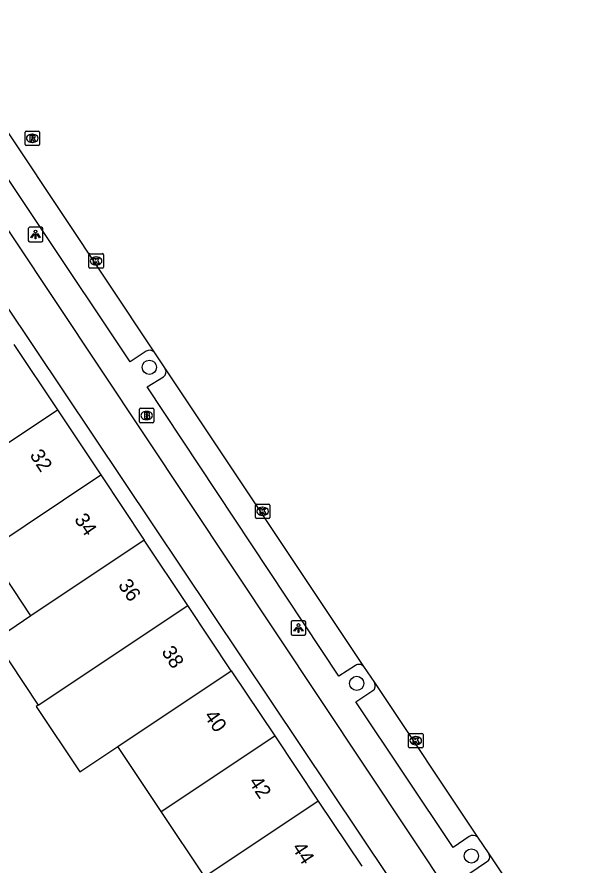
# Model space of a CAD drawing. Extents: x 158352 to 159489, y 383828 to 384597.
# Drawn here: x 158924.3 to 158963.6, y 384353.8 to 384412.1 of the extents above; entities that cross this region are included whole.
import ezdxf

# ---------------------------------------------------------------- set-up
doc = ezdxf.new("R2010")
doc.units = 0
for name, color, linetype in [('IMGEO_Boom', 7, 'Continuous'), ('IMGEO_Brandkraan', 7, 'Continuous'), ('IMGEO_Erf', 7, 'Continuous'), ('IMGEO_Kolk', 7, 'Continuous'), ('IMGEO_Lichtpunt', 7, 'Continuous'), ('IMGEO_Pand', 7, 'Continuous'), ('IMGEO_Pand_nummerreeks', 7, 'Continuous'), ('IMGEO_Rijbaan_lokaal_gesloten', 7, 'Continuous'), ('IMGEO_Rioolput', 7, 'Continuous'), ('IMGEO_Voetpad_open', 7, 'Continuous')]:
    doc.layers.add(name, color=color, linetype=linetype)

msp = doc.modelspace()

# ---------------------------------------------------------------- linework, layer by layer
at = {"layer": 'IMGEO_Boom'}
for centre in [(158933.366, 384388.02), (158947.643, 384366.263), (158955.538, 384354.394)]:
    msp.add_circle(centre, 0.489, dxfattribs=at)
at = {"layer": 'IMGEO_Brandkraan'}
for p, q in [((158932.682, 384384.272), (158932.682, 384385.124)), ((158932.757, 384385.198), (158933.609, 384385.198)), ((158933.17, 384384.978), (158933.195, 384384.978)), ((158933.683, 384385.124), (158933.683, 384384.272)), ((158933.609, 384384.198), (158932.757, 384384.198)), ((158933.193, 384384.418), (158933.168, 384384.418))]:
    msp.add_line(p, q, dxfattribs=at)
for points in [[(158932.682, 384384.272), (158932.682, 384385.124)], [(158932.757, 384385.198), (158933.609, 384385.198)], [(158933.03, 384384.898), (158933.03, 384384.498), (158933.243, 384384.498)], [(158933.261, 384384.898), (158933.03, 384384.898)], [(158933.209, 384384.817), (158933.155, 384384.817), (158933.155, 384384.741)], [(158933.155, 384384.741), (158933.208, 384384.741)], [(158933.217, 384384.665), (158933.155, 384384.665), (158933.155, 384384.584)], [(158933.683, 384385.124), (158933.683, 384384.272)], [(158933.609, 384384.198), (158932.757, 384384.198)], [(158933.155, 384384.584), (158933.217, 384384.584)]]:
    msp.add_lwpolyline(points, dxfattribs=at)
for centre, radius, start, end in [((158932.759, 384385.122), 0.0765, 91.55205, 178.44795), ((158932.759, 384385.122), 0.0765, 91.55205, 178.44795), ((158933.21, 384384.779), 0.0379, 267.82845, 90.93552), ((158933.218, 384384.624), 0.0404, 269.87594, 90.50774), ((158933.265, 384384.753), 0.145, 59.4692, 91.53667), ((158933.29, 384384.8), 0.0922, 285.51372, 58.15012), ((158933.295, 384384.608), 0.105, 301.31148, 78.98903), ((158933.607, 384385.122), 0.0765, 1.55205, 88.44795), ((158933.607, 384385.122), 0.0765, 1.55205, 88.44795), ((158932.759, 384384.274), 0.0765, 181.55205, 268.44795), ((158932.759, 384384.274), 0.0765, 181.55205, 268.44795), ((158933.249, 384384.749), 0.251, 268.66757, 293.53466), ((158933.607, 384384.274), 0.0765, 271.55205, 358.44795), ((158933.607, 384384.274), 0.0765, 271.55205, 358.44795)]:
    msp.add_arc(centre, radius, start, end, dxfattribs=at)
for centre, major_axis, ratio, start_param, end_param in [((158933.169, 384384.698), (-0.387, 0.002), 0.722429, 4.712389, 7.853982), ((158933.194, 384384.698), (-0.39, 0.002), 0.717154, 1.570796, 4.712389)]:
    msp.add_ellipse(centre, major_axis=major_axis, ratio=ratio, start_param=start_param, end_param=end_param, dxfattribs=at)
at = {"layer": 'IMGEO_Erf'}
msp.add_lwpolyline([(158958.047, 384340.708), (158896.943, 384431.973), (158882.708, 384453.235)], dxfattribs=at)
at = {"layer": 'IMGEO_Kolk'}
for p, q in [((158929.198, 384394.909), (158929.198, 384395.761)), ((158929.273, 384395.835), (158930.125, 384395.835)), ((158930.199, 384395.761), (158930.199, 384394.909)), ((158929.686, 384395.615), (158929.711, 384395.615)), ((158930.125, 384394.835), (158929.273, 384394.835)), ((158929.709, 384395.055), (158929.684, 384395.055)), ((158940.665, 384377.68), (158940.665, 384378.532)), ((158940.74, 384378.606), (158941.592, 384378.606)), ((158941.153, 384378.386), (158941.178, 384378.386)), ((158941.666, 384378.532), (158941.666, 384377.68)), ((158941.176, 384377.826), (158941.151, 384377.826)), ((158941.592, 384377.606), (158940.74, 384377.606)), ((158951.209, 384361.901), (158951.209, 384362.753)), ((158951.284, 384362.827), (158952.136, 384362.827)), ((158951.697, 384362.607), (158951.722, 384362.607)), ((158952.21, 384362.753), (158952.21, 384361.901)), ((158951.72, 384362.047), (158951.695, 384362.047)), ((158952.136, 384361.827), (158951.284, 384361.827))]:
    msp.add_line(p, q, dxfattribs=at)
for points in [[(158929.198, 384394.909), (158929.198, 384395.761)], [(158929.273, 384395.835), (158930.125, 384395.835)], [(158930.199, 384395.761), (158930.199, 384394.909)], [(158929.519, 384395.535), (158929.642, 384395.535), (158929.642, 384395.384), (158929.772, 384395.535), (158929.936, 384395.535), (158929.79, 384395.384), (158929.943, 384395.135), (158929.791, 384395.135), (158929.706, 384395.299), (158929.642, 384395.232), (158929.642, 384395.135), (158929.519, 384395.135), (158929.519, 384395.535)], [(158930.125, 384394.835), (158929.273, 384394.835)], [(158940.665, 384377.68), (158940.665, 384378.532)], [(158940.74, 384378.606), (158941.592, 384378.606)], [(158940.986, 384378.306), (158941.109, 384378.306), (158941.109, 384378.155), (158941.239, 384378.306), (158941.403, 384378.306), (158941.257, 384378.155), (158941.41, 384377.906), (158941.258, 384377.906), (158941.173, 384378.07), (158941.109, 384378.003), (158941.109, 384377.906), (158940.986, 384377.906), (158940.986, 384378.306)], [(158941.666, 384378.532), (158941.666, 384377.68)], [(158941.592, 384377.606), (158940.74, 384377.606)], [(158951.209, 384361.901), (158951.209, 384362.753)], [(158951.284, 384362.827), (158952.136, 384362.827)], [(158951.53, 384362.527), (158951.653, 384362.527), (158951.653, 384362.376), (158951.783, 384362.527), (158951.947, 384362.527), (158951.801, 384362.376), (158951.954, 384362.127), (158951.802, 384362.127), (158951.717, 384362.291), (158951.653, 384362.224), (158951.653, 384362.127), (158951.53, 384362.127), (158951.53, 384362.527)], [(158952.21, 384362.753), (158952.21, 384361.901)], [(158952.136, 384361.827), (158951.284, 384361.827)]]:
    msp.add_lwpolyline(points, dxfattribs=at)
for centre, start, end in [((158929.275, 384395.759), 91.55205, 178.44795), ((158929.275, 384395.759), 91.55205, 178.44795), ((158930.123, 384395.759), 1.55205, 88.44795), ((158930.123, 384395.759), 1.55205, 88.44795), ((158929.275, 384394.911), 181.55205, 268.44795), ((158929.275, 384394.911), 181.55205, 268.44795), ((158930.123, 384394.911), 271.55205, 358.44795), ((158930.123, 384394.911), 271.55205, 358.44795), ((158940.742, 384378.53), 91.55205, 178.44795), ((158940.742, 384378.53), 91.55205, 178.44795), ((158941.59, 384378.53), 1.55205, 88.44795), ((158941.59, 384378.53), 1.55205, 88.44795), ((158940.742, 384377.682), 181.55205, 268.44795), ((158940.742, 384377.682), 181.55205, 268.44795), ((158941.59, 384377.682), 271.55205, 358.44795), ((158941.59, 384377.682), 271.55205, 358.44795), ((158951.286, 384362.751), 91.55205, 178.44795), ((158951.286, 384362.751), 91.55205, 178.44795), ((158952.134, 384362.751), 1.55205, 88.44795), ((158952.134, 384362.751), 1.55205, 88.44795), ((158951.286, 384361.903), 181.55205, 268.44795), ((158951.286, 384361.903), 181.55205, 268.44795), ((158952.134, 384361.903), 271.55205, 358.44795), ((158952.134, 384361.903), 271.55205, 358.44795)]:
    msp.add_arc(centre, 0.0765, start, end, dxfattribs=at)
for centre, major_axis, ratio, start_param, end_param in [((158929.685, 384395.335), (-0.387, 0.002), 0.722429, 4.712389, 7.853982), ((158929.71, 384395.335), (-0.39, 0.002), 0.717154, 1.570796, 4.712389), ((158941.152, 384378.106), (-0.387, 0.002), 0.722429, 4.712389, 7.853982), ((158941.177, 384378.106), (-0.39, 0.002), 0.717154, 1.570796, 4.712389), ((158951.696, 384362.327), (-0.387, 0.002), 0.722429, 4.712389, 7.853982), ((158951.721, 384362.327), (-0.39, 0.002), 0.717154, 1.570796, 4.712389)]:
    msp.add_ellipse(centre, major_axis=major_axis, ratio=ratio, start_param=start_param, end_param=end_param, dxfattribs=at)
at = {"layer": 'IMGEO_Lichtpunt'}
for p, q in [((158925.032, 384397.557), (158925.032, 384396.75)), ((158925.032, 384397.557), (158925.032, 384396.75)), ((158925.934, 384397.652), (158925.126, 384397.652)), ((158925.934, 384397.652), (158925.126, 384397.652)), ((158926.028, 384396.75), (158926.028, 384397.557)), ((158926.028, 384396.75), (158926.028, 384397.557)), ((158925.126, 384396.656), (158925.934, 384396.656)), ((158925.126, 384396.656), (158925.934, 384396.656)), ((158943.136, 384370.481), (158943.136, 384369.674)), ((158943.136, 384370.481), (158943.136, 384369.674)), ((158944.038, 384370.576), (158943.23, 384370.576)), ((158944.038, 384370.576), (158943.23, 384370.576)), ((158944.132, 384369.674), (158944.132, 384370.481)), ((158944.132, 384369.674), (158944.132, 384370.481)), ((158943.23, 384369.58), (158944.038, 384369.58)), ((158943.23, 384369.58), (158944.038, 384369.58))]:
    msp.add_line(p, q, dxfattribs=at)
for points in [[(158925.406, 384397.221), (158925.445, 384397.193), (158925.257, 384396.931), (158925.219, 384396.958), (158925.406, 384397.221)], [(158925.508, 384397.173), (158925.555, 384397.173), (158925.555, 384396.851), (158925.508, 384396.851), (158925.508, 384397.173)], [(158925.618, 384397.193), (158925.656, 384397.22), (158925.843, 384396.958), (158925.804, 384396.93), (158925.618, 384397.193)], [(158943.51, 384370.145), (158943.549, 384370.117), (158943.361, 384369.855), (158943.323, 384369.882), (158943.51, 384370.145)], [(158943.612, 384370.097), (158943.659, 384370.097), (158943.659, 384369.775), (158943.612, 384369.775), (158943.612, 384370.097)], [(158943.722, 384370.117), (158943.76, 384370.144), (158943.947, 384369.882), (158943.908, 384369.854), (158943.722, 384370.117)]]:
    msp.add_lwpolyline(points, dxfattribs=at)
for centre in [(158925.531, 384397.355), (158943.635, 384370.279)]:
    msp.add_circle(centre, 0.0994, dxfattribs=at)
for centre, start, end in [((158925.126, 384397.557), 90, 180), ((158925.126, 384397.557), 90, 180), ((158925.934, 384397.557), 0, 90), ((158925.934, 384397.557), 0, 90), ((158925.126, 384396.75), 180, 270), ((158925.126, 384396.75), 180, 270), ((158925.934, 384396.75), 270, 0), ((158925.934, 384396.75), 270, 360), ((158943.23, 384370.481), 90, 180), ((158943.23, 384370.481), 90, 180), ((158944.038, 384370.481), 0, 90), ((158944.038, 384370.481), 0, 90), ((158943.23, 384369.674), 180, 270), ((158943.23, 384369.674), 180, 270), ((158944.038, 384369.674), 270, 0), ((158944.038, 384369.674), 270, 360)]:
    msp.add_arc(centre, 0.0946, start, end, dxfattribs=at)
at = {"layer": 'IMGEO_Pand'}
for points in [[(158924.033, 384389.586), (158927.032, 384385.093)], [(158919.225, 384379.892), (158927.032, 384385.093)], [(158927.032, 384385.093), (158930.022, 384380.611)], [(158922.215, 384375.409), (158930.022, 384380.611)], [(158930.022, 384380.611), (158933.021, 384376.115)], [(158933.021, 384376.115), (158925.212, 384370.913)], [(158936.009, 384371.634), (158933.021, 384376.115)], [(158925.212, 384370.913), (158922.215, 384375.409)], [(158925.707, 384364.769), (158936.009, 384371.634)], [(158939.008, 384367.138), (158936.009, 384371.634)], [(158925.212, 384370.913), (158922.719, 384369.251), (158925.707, 384364.769)], [(158931.198, 384361.934), (158939.008, 384367.138)], [(158939.008, 384367.138), (158941.997, 384362.657)], [(158925.707, 384364.769), (158925.581, 384364.685), (158928.579, 384360.189), (158931.198, 384361.934)], [(158934.185, 384357.453), (158941.997, 384362.657)], [(158941.997, 384362.657), (158944.995, 384358.163)], [(158934.185, 384357.453), (158931.198, 384361.934)], [(158944.995, 384358.163), (158937.182, 384352.958)], [(158944.995, 384358.163), (158947.985, 384353.68)], [(158937.182, 384352.958), (158934.185, 384357.453)]]:
    msp.add_lwpolyline(points, dxfattribs=at)
at = {"layer": 'IMGEO_Rijbaan_lokaal_gesloten'}
for points in [[(158920.763, 384408.459), (158933.684, 384389.073)], [(158933.684, 384389.073), (158934.462, 384387.903)], [(158934.462, 384387.903), (158948.108, 384367.417)], [(158948.108, 384367.417), (158948.862, 384366.323)], [(158948.862, 384366.323), (158955.957, 384355.688)], [(158955.957, 384355.688), (158956.746, 384354.542)], [(158956.746, 384354.542), (158963.568, 384344.252)]]:
    msp.add_lwpolyline(points, dxfattribs=at)
at = {"layer": 'IMGEO_Rioolput'}
for p, q in [((158924.807, 384403.348), (158924.807, 384404.2)), ((158924.882, 384404.274), (158925.734, 384404.274)), ((158925.295, 384404.054), (158925.32, 384404.054)), ((158925.808, 384404.2), (158925.808, 384403.348)), ((158925.318, 384403.494), (158925.293, 384403.494)), ((158925.734, 384403.274), (158924.882, 384403.274))]:
    msp.add_line(p, q, dxfattribs=at)
for points in [[(158924.807, 384403.348), (158924.807, 384404.2)], [(158924.882, 384404.274), (158925.734, 384404.274)], [(158925.396, 384403.972), (158925.144, 384403.974), (158925.144, 384403.574)], [(158925.808, 384404.2), (158925.808, 384403.348)], [(158925.144, 384403.574), (158925.268, 384403.574), (158925.268, 384403.736), (158925.279, 384403.736)], [(158925.322, 384403.893), (158925.268, 384403.893), (158925.268, 384403.812)], [(158925.268, 384403.812), (158925.32, 384403.812)], [(158925.326, 384403.707), (158925.397, 384403.574), (158925.537, 384403.574), (158925.472, 384403.7)], [(158925.734, 384403.274), (158924.882, 384403.274)]]:
    msp.add_lwpolyline(points, dxfattribs=at)
for centre, radius, start, end in [((158924.884, 384404.198), 0.0765, 91.55205, 178.44795), ((158924.884, 384404.198), 0.0765, 91.55205, 178.44795), ((158925.395, 384403.862), 0.109, 350.36119, 89.41601), ((158925.732, 384404.198), 0.0765, 1.55205, 88.44795), ((158925.732, 384404.198), 0.0765, 1.55205, 88.44795), ((158924.884, 384403.35), 0.0765, 181.55205, 268.44795), ((158924.884, 384403.35), 0.0765, 181.55205, 268.44795), ((158925.278, 384403.683), 0.0533, 26.02933, 88.69889), ((158925.304, 384404.001), 0.19, 274.7715, 282.96867), ((158925.328, 384403.797), 0.0964, 77.00612, 93.18647), ((158925.342, 384403.854), 0.0378, 276.66336, 79.67722), ((158925.393, 384403.862), 0.112, 277.58423, 350.98172), ((158925.377, 384403.647), 0.108, 29.51342, 73.79051), ((158925.732, 384403.35), 0.0765, 271.55205, 358.44795), ((158925.732, 384403.35), 0.0765, 271.55205, 358.44795)]:
    msp.add_arc(centre, radius, start, end, dxfattribs=at)
for centre, major_axis, ratio, start_param, end_param in [((158925.294, 384403.774), (-0.387, 0.002), 0.722429, 4.712389, 7.853982), ((158925.319, 384403.774), (-0.39, 0.002), 0.717154, 1.570796, 4.712389)]:
    msp.add_ellipse(centre, major_axis=major_axis, ratio=ratio, start_param=start_param, end_param=end_param, dxfattribs=at)
at = {"layer": 'IMGEO_Voetpad_open'}
for points in [[(158885.345, 384454.99), (158899.598, 384433.573), (158960.345, 384342.297)], [(158933.158, 384389.116), (158932.053, 384388.385), (158919.498, 384407.15), (158920.652, 384407.923)], [(158947.569, 384367.491), (158946.419, 384366.755), (158933.215, 384386.663), (158934.332, 384387.359)], [(158955.379, 384355.738), (158954.28, 384354.983), (158947.59, 384364.999), (158948.742, 384365.766)], [(158962.439, 384343.965), (158961.889, 384343.592), (158955.43, 384353.212), (158956.581, 384353.981)]]:
    msp.add_lwpolyline(points, dxfattribs=at)
for centre, radius, start, end in [((158933.395, 384388.771), 0.418, 46.17331, 124.47973), ((158934.123, 384387.697), 0.397, 301.7806, 31.3395), ((158947.805, 384367.211), 0.366, 34.17761, 130.18772), ((158948.522, 384366.105), 0.404, 302.9879, 32.69616), ((158955.632, 384355.3), 0.506, 50.09573, 120.01613), ((158956.384, 384354.344), 0.413, 298.47912, 28.7418)]:
    msp.add_arc(centre, radius, start, end, dxfattribs=at)

# ---------------------------------------------------------------- texts
at = {"layer": 'IMGEO_Pand_nummerreeks'}
for s, rotation, p in [('32', 303.23864, (158925.098, 384381.97)), ('34', 304.27832, (158928.16, 384377.549)), ('36', 304.85281, (158931.18, 384373.023)), ('38', 303.10529, (158934.168, 384368.442)), ('40', 304.81587, (158937.095, 384364.025)), ('42', 303.253, (158940.174, 384359.485)), ('44', 303.12132, (158943.146, 384354.957))]:
    msp.add_text(s, height=1, rotation=rotation, dxfattribs=at).set_placement(p)

doc.saveas('drawing.dxf')
